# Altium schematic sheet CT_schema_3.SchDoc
size 282 x 147 mm
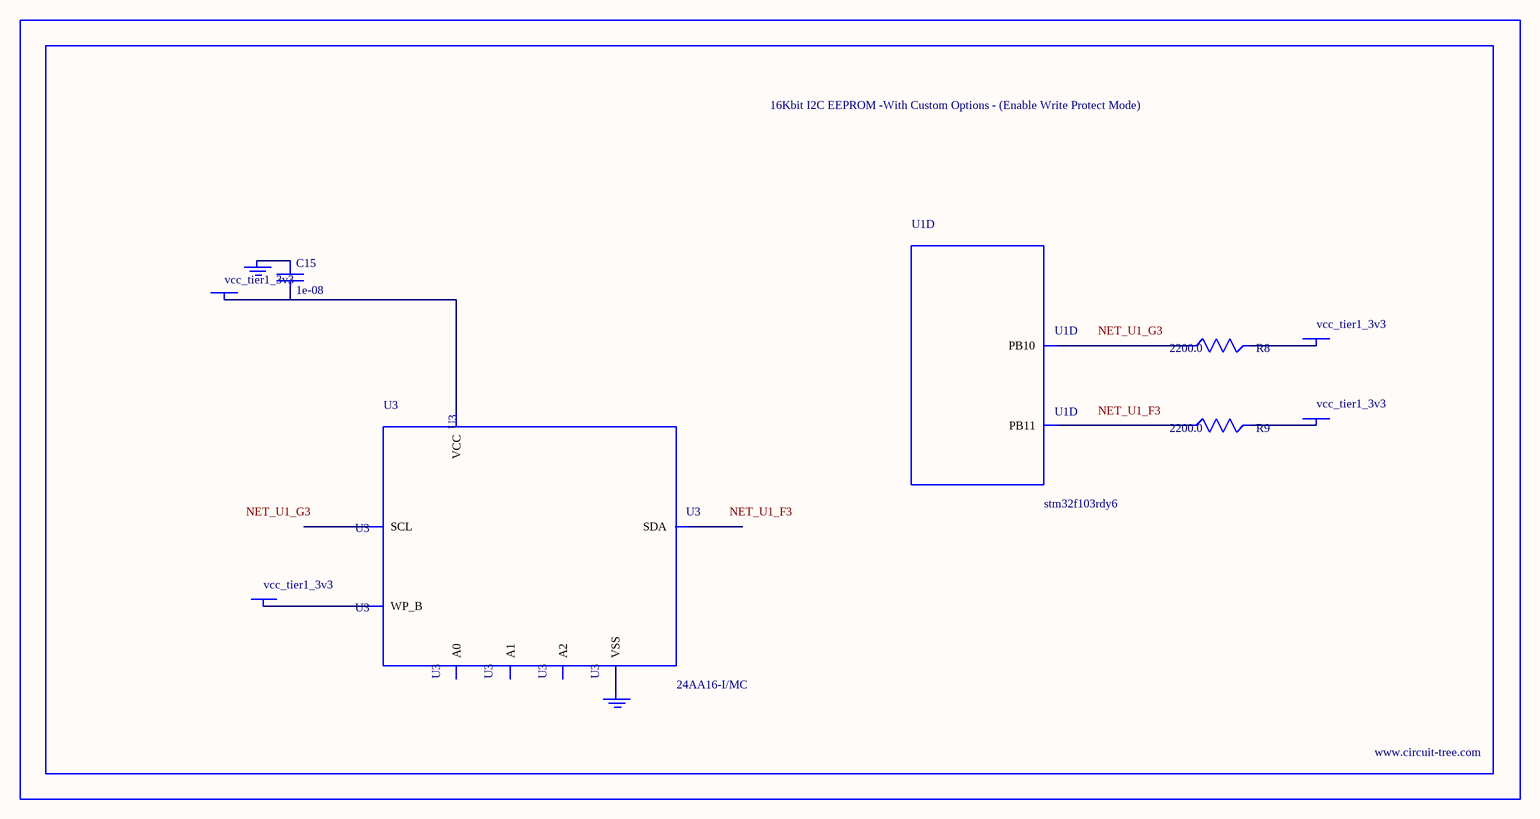
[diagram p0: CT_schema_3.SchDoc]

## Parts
BORDER2  (no value)
C15  1e-08  [C0402]
GND_INSTANCE_2_0  (no value)
GND_INSTANCE_2_1  (no value)
POWER_INSTANCE_2_0  vcc_tier1_3v3
POWER_INSTANCE_2_1  vcc_tier1_3v3
POWER_INSTANCE_2_2  vcc_tier1_3v3
POWER_INSTANCE_2_3  vcc_tier1_3v3
R8  2200.0  [R0603]
R9  2200.0  [R0603]
U1  stm32f103rdy6  [WLCSP64]  (part D of 7)
U3  24AA16-I/MC  [TDFN-8/6MM]

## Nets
NetC15_1: C15.1 GND_INSTANCE_2_0.0(GND)
NetC15_2: C15.2 POWER_INSTANCE_2_1.0(PWR) U3.8(VCC)
NetGND_INSTANCE_2_1_0: GND_INSTANCE_2_1.0(GND) U3.4(VSS)
NetPOWER_INSTANCE_2_0_0: POWER_INSTANCE_2_0.0(PWR) U3.7(WP_B)
NetPOWER_INSTANCE_2_2_0: POWER_INSTANCE_2_2.0(PWR) R8.2
NetPOWER_INSTANCE_2_3_0: POWER_INSTANCE_2_3.0(PWR) R9.2
NetR8_1: R8.1 U1.G3(PB10)
NetR9_1: R9.1 U1.F3(PB11)

Not connected (* = marked no-connect by the designer): U3 1(A0) 2(A1) 3(A2) 5(SDA) 6(SCL)

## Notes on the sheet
- Labels drawn without touching a wire or pin: NET_U1_F3, NET_U1_G3

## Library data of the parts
BORDER2 = BORDER_PAGE2
C15 = C0402C103K3RAC
GND_INSTANCE_2_0 GND_INSTANCE_2_1 = GND
POWER_INSTANCE_2_0-POWER_INSTANCE_2_3 = PWR
R8 R9 = RC0603JR-072K2L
